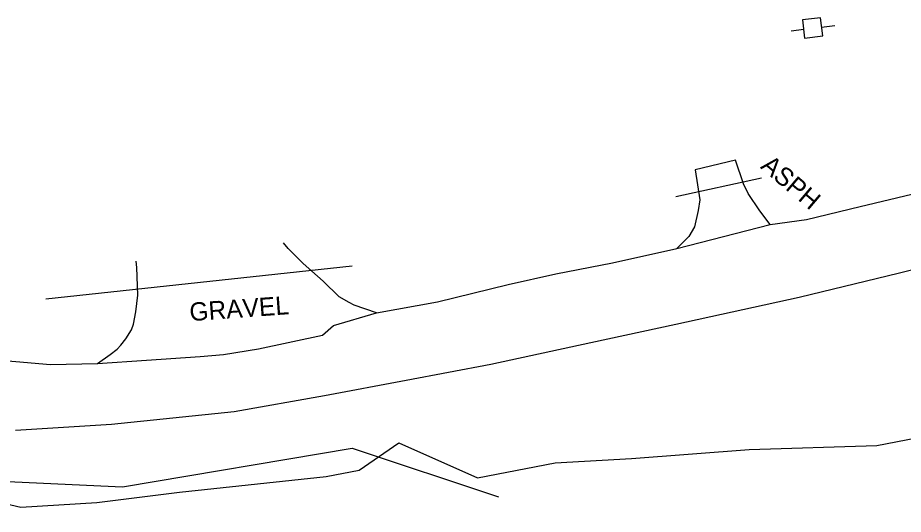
# Model space of a CAD drawing. Extents: x 2076109 to 2080761, y 592812 to 596750.
# Drawn here: x 2077285.2 to 2077526.3, y 596021.2 to 596156.3 of the extents above; entities that cross this region are included whole.
import ezdxf

# ---------------------------------------------------------------- set-up
doc = ezdxf.new("R2010")
doc.units = 0
for name, color, linetype in [('RD_EX_DR_Pipe', 7, 'Continuous'), ('RD_EX_Driveway', 7, 'Continuous'), ('RD_EX_Driveway_txCode', 7, 'Continuous'), ('RD_EX_Fence_ChLk', 7, 'Continuous'), ('RD_EX_Road', 7, 'Continuous'), ('RD_EX_UT', 7, 'Continuous'), ('RD_EX_VEG', 7, 'Continuous')]:
    doc.layers.add(name, color=color, linetype=linetype)

msp = doc.modelspace()

# ---------------------------------------------------------------- linework, layer by layer
at = {"layer": 'RD_EX_DR_Pipe'}
for p, q in [((2077464.34, 596107.7), (2077487.74, 596112.71)), ((2077464.34, 596107.7), (2077487.74, 596112.71)), ((2077292.9, 596079.79), (2077376.27, 596088.79)), ((2077292.9, 596079.79), (2077376.27, 596088.79))]:
    msp.add_line(p, q, dxfattribs=at)
at = {"layer": 'RD_EX_Driveway'}
for points in [[(2077490.07, 596100.07), (2077487.21, 596103.81), (2077484.09, 596108.49), (2077482.83, 596111.13), (2077480.66, 596117.59), (2077469.66, 596114.95), (2077470.92, 596106.78), (2077470.46, 596103.85), (2077469.47, 596099.43), (2077467.95, 596096.79), (2077464.65, 596093.51)], [(2077490.07, 596100.07), (2077487.21, 596103.81), (2077484.09, 596108.49), (2077482.83, 596111.13), (2077480.66, 596117.59), (2077469.66, 596114.95), (2077470.92, 596106.78), (2077470.46, 596103.85), (2077469.47, 596099.43), (2077467.95, 596096.79), (2077464.65, 596093.51)], [(2077382.89, 596076.04), (2077376.84, 596078.09), (2077375.43, 596078.83), (2077372.71, 596080.4), (2077368.34, 596084.58), (2077362.96, 596089.43), (2077358.89, 596093.54), (2077357.57, 596095.09)], [(2077382.89, 596076.04), (2077376.84, 596078.09), (2077375.43, 596078.83), (2077372.71, 596080.4), (2077368.34, 596084.58), (2077362.96, 596089.43), (2077358.89, 596093.54), (2077357.57, 596095.09)], [(2077306.99, 596062.22), (2077310.38, 596064.69), (2077312.31, 596066.09), (2077313.26, 596067.21), (2077314.67, 596068.97), (2077316.22, 596071.34), (2077316.74, 596072.93), (2077317.41, 596076.32), (2077317.94, 596080.85), (2077317.64, 596088.31), (2077317.45, 596090.06)], [(2077306.99, 596062.22), (2077310.38, 596064.69), (2077312.31, 596066.09), (2077313.26, 596067.21), (2077314.67, 596068.97), (2077316.22, 596071.34), (2077316.74, 596072.93), (2077317.41, 596076.32), (2077317.94, 596080.85), (2077317.64, 596088.31), (2077317.45, 596090.06)]]:
    msp.add_lwpolyline(points, dxfattribs=at)
at = {"layer": 'RD_EX_Fence_ChLk'}
msp.add_lwpolyline([(2077268.73, 596030.73), (2077313.72, 596028.64), (2077376.27, 596039.18), (2077416.08, 596025.9)], dxfattribs=at)
msp.add_lwpolyline([(2077268.73, 596030.73), (2077313.72, 596028.64), (2077376.27, 596039.18), (2077416.08, 596025.9)], dxfattribs=at)
at = {"layer": 'RD_EX_Road'}
for points in [[(2077645.43, 596113.93), (2077610.05, 596105.64), (2077584.56, 596100.66), (2077560.11, 596095.44), (2077525.26, 596086.84), (2077497.93, 596080.19), (2077464.38, 596072.84), (2077441.23, 596067.85), (2077413.99, 596061.96), (2077390.93, 596057.62), (2077368.72, 596053.41), (2077344.12, 596049.05), (2077310.8, 596045.6), (2077284.61, 596043.93)], [(2077645.43, 596113.93), (2077610.05, 596105.64), (2077584.56, 596100.66), (2077560.11, 596095.44), (2077525.26, 596086.84), (2077497.93, 596080.19), (2077464.38, 596072.84), (2077441.23, 596067.85), (2077413.99, 596061.96), (2077390.93, 596057.62), (2077368.72, 596053.41), (2077344.12, 596049.05), (2077310.8, 596045.6), (2077284.61, 596043.93)], [(2077275.23, 596063.54), (2077294.18, 596061.91), (2077306.99, 596062.22), (2077320.3, 596063.13), (2077334.9, 596064.13), (2077341.28, 596064.7), (2077350.73, 596066.21), (2077368.21, 596069.9), (2077371.18, 596072.53), (2077382.89, 596076.04), (2077399.5, 596079.03), (2077418.76, 596083.73), (2077431.73, 596086.63), (2077447.15, 596089.57), (2077464.65, 596093.51), (2077490.07, 596100.07), (2077499.98, 596101.42), (2077514.57, 596104.92), (2077534.69, 596109.77)], [(2077275.23, 596063.54), (2077294.18, 596061.91), (2077306.99, 596062.22), (2077320.3, 596063.13), (2077334.9, 596064.13), (2077341.28, 596064.7), (2077350.73, 596066.21), (2077368.21, 596069.9), (2077371.18, 596072.53), (2077382.89, 596076.04), (2077399.5, 596079.03), (2077418.76, 596083.73), (2077431.73, 596086.63), (2077447.15, 596089.57), (2077464.65, 596093.51), (2077490.07, 596100.07), (2077499.98, 596101.42), (2077514.57, 596104.92), (2077534.69, 596109.77)]]:
    msp.add_lwpolyline(points, dxfattribs=at)
at = {"layer": 'RD_EX_UT'}
for p, q in [((2077503.8, 596156.34), (2077498.84, 596155.74)), ((2077503.8, 596156.34), (2077498.84, 596155.74)), ((2077504.4, 596151.38), (2077503.8, 596156.34)), ((2077504.4, 596151.38), (2077503.8, 596156.34)), ((2077498.84, 596155.74), (2077499.44, 596150.78)), ((2077498.84, 596155.74), (2077499.44, 596150.78)), ((2077504.04, 596153.79), (2077507.65, 596154.22)), ((2077504.04, 596153.79), (2077507.65, 596154.22)), ((2077495.74, 596152.79), (2077499.18, 596153.2)), ((2077495.74, 596152.79), (2077499.18, 596153.2)), ((2077499.44, 596150.78), (2077504.4, 596151.38)), ((2077499.44, 596150.78), (2077504.4, 596151.38))]:
    msp.add_line(p, q, dxfattribs=at)
at = {"layer": 'RD_EX_VEG'}
for points in [[(2077452.32, 596036.38), (2077484.3, 596038.76), (2077519.05, 596039.86), (2077543.06, 596044.55), (2077554.7, 596042.23), (2077566.69, 596033.37), (2077573.01, 596026.73), (2077575.87, 596012.73), (2077573.1, 596007.72), (2077559.2, 595996.51), (2077543.73, 595991.04), (2077514.3, 595984.51), (2077495.27, 595976.35), (2077457.35, 595967.82), (2077431.71, 595951.64)], [(2077452.32, 596036.38), (2077484.3, 596038.76), (2077519.05, 596039.86), (2077543.06, 596044.55), (2077554.7, 596042.23), (2077566.69, 596033.37), (2077573.01, 596026.73), (2077575.87, 596012.73), (2077573.1, 596007.72), (2077559.2, 595996.51), (2077543.73, 595991.04), (2077514.3, 595984.51), (2077495.27, 595976.35), (2077457.35, 595967.82), (2077431.71, 595951.64)], [(2077249.3, 596031.71), (2077286.09, 596023.13), (2077306.73, 596024.4), (2077329.23, 596027.22), (2077369.17, 596031.44), (2077378.2, 596033.17), (2077388.96, 596040.62), (2077410.37, 596031.09), (2077431.57, 596035.2), (2077452.32, 596036.38)], [(2077249.3, 596031.71), (2077286.09, 596023.13), (2077306.73, 596024.4), (2077329.23, 596027.22), (2077369.17, 596031.44), (2077378.2, 596033.17), (2077388.96, 596040.62), (2077410.37, 596031.09), (2077431.57, 596035.2), (2077452.32, 596036.38)]]:
    msp.add_lwpolyline(points, dxfattribs=at)

# ---------------------------------------------------------------- texts
at = {"layer": 'RD_EX_Driveway_txCode'}
for s, rotation, p in [('ASPH', 319.6274, (2077487.19, 596115.53)), ('ASPH', 319.6274, (2077487.19, 596115.53)), ('GRAVEL', 4.0648, (2077332.15, 596073.72)), ('GRAVEL', 4.0648, (2077332.15, 596073.72))]:
    msp.add_text(s, height=5, rotation=rotation, dxfattribs=at).set_placement(p)

doc.saveas('drawing.dxf')
